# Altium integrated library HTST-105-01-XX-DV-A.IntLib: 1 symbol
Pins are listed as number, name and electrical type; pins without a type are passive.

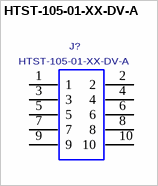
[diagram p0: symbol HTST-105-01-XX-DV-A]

## HTST-105-01-XX-DV-A
designator J?
HIGH TEMP TOP SHROUD; MANUFACTURER: SAMTEC
footprint HTST-105-01-XX-DV-A
pins: 1, 2, 3, 4, 5, 6, 7, 8, 9, 10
